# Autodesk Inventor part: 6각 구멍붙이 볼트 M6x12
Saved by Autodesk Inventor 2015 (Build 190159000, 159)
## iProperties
Created: 2025-06
Part Number: 6각 구멍붙이 볼트 M6x12
Material: 일반
Document SubType Name: Modeling
Designer: User
Density: 1 g/cm^3
Appearance: 기본값
Author: User
Author: jhkim
Description: 6각머리 태핑 나사
Creation Date: 2025-05-23
Sending System: Autodesk Inventor 2026
Preprocessor: ST-DEVELOPER v20.1
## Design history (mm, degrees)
node "6각 구멍붙이 볼트 M6x121"
body "Solid1"
node "기준1"
